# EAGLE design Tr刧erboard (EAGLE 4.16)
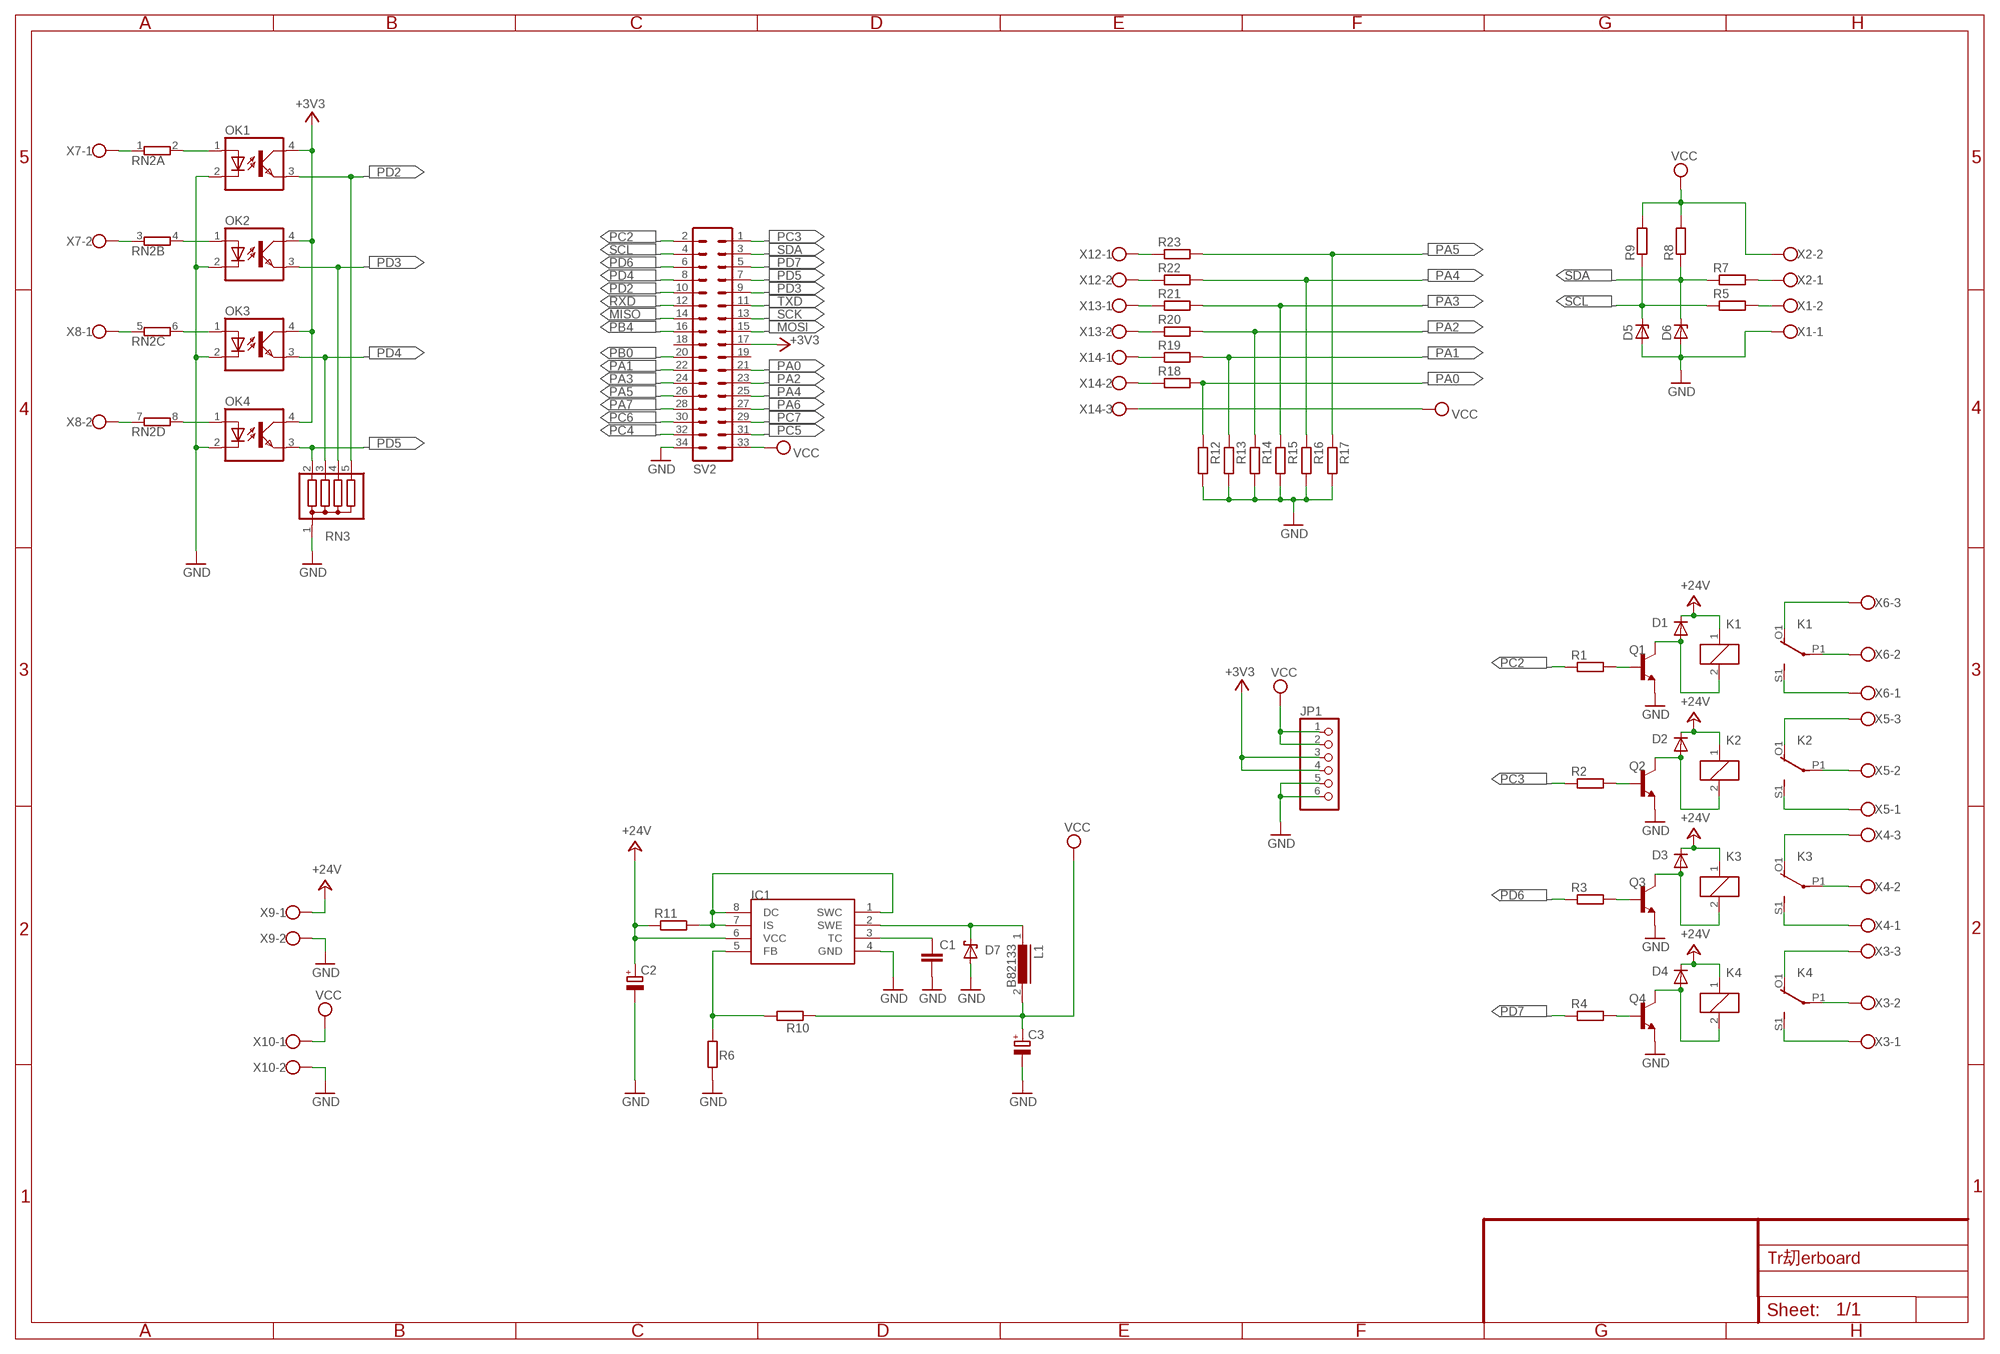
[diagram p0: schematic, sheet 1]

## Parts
C1  C-EU025-024X044  [C025-024X044]
C2  CPOL-EUE5-8.5  [E5-8,5]
C3  CPOL-EUE5-8.5  [E5-8,5]
D1  1N4148  [DO35-10]
D2  1N4148  [DO35-10]
D3  1N4148  [DO35-10]
D4  1N4148  [DO35-10]
D5  1N821  [DO35Z10]
D6  1N821  [DO35Z10]
D7  BAT49  [DO41-10]
IC1  MC34063AP  [DIL08]
JP1  PINHD-1X6  [1X06]
K1  4052  [F4052]
K2  4052  [F4052]
K3  4052  [F4052]
K4  4052  [F4052]
L1  B82133  [SUKW3-27]
OK1  PC817  [DIL04]
OK2  PC817  [DIL04]
OK3  PC817  [DIL04]
OK4  PC817  [DIL04]
Q1  BC337  [TO92]
Q2  BC337  [TO92]
Q3  BC337  [TO92]
Q4  BC337  [TO92]
R1  R-EU_0207/10  [0207/10]
R2  R-EU_0207/10  [0207/10]
R3  R-EU_0207/10  [0207/10]
R4  R-EU_0207/10  [0207/10]
R5  R-EU_0207/10  [0207/10]
R6  R-EU_0207/10  [0207/10]
R7  R-EU_0207/10  [0207/10]
R8  R-EU_0207/10  [0207/10]
R9  R-EU_0207/10  [0207/10]
R10  R-EU_0207/10  [0207/10]
R11  R-EU_0613/15  [P0613/15]
R12  R-EU_0207/10  [0207/10]
R13  R-EU_0207/10  [0207/10]
R14  R-EU_0207/10  [0207/10]
R15  R-EU_0207/10  [0207/10]
R16  R-EU_0207/10  [0207/10]
R17  R-EU_0207/10  [0207/10]
R18  R-EU_0207/10  [0207/10]
R19  R-EU_0207/10  [0207/10]
R20  R-EU_0207/10  [0207/10]
R21  R-EU_0207/10  [0207/10]
R22  R-EU_0207/10  [0207/10]
R23  R-EU_0207/10  [0207/10]
RN2  E4R  [SIL8]
RN3  G04R  [SIL5]
SV2  MA17-2  [MA17-2]
X1  W237-02P  [W237-132]
X2  W237-02P  [W237-132]
X3  W237-103  [W237-103]
X4  W237-103  [W237-103]
X5  W237-103  [W237-103]
X6  W237-103  [W237-103]
X7  W237-02P  [W237-132]
X8  W237-02P  [W237-132]
X9  W237-02P  [W237-132]
X10  W237-02P  [W237-132]
X12  W237-02P  [W237-132]
X13  W237-02P  [W237-132]
X14  W237-3E  [W237-3E]

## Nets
+3V3: JP1.3 JP1.4 OK1.4(COL) OK2.4(COL) OK3.4(COL) OK4.4(COL) SV2.17
+24V: C2.+ D1.C D2.C D3.C D4.C IC1.6(VCC) K1.1 K2.1 K3.1 K4.1 R11.1 X9.1
GND: C1.2 C2.- C3.- D5.A D6.A D7.A IC1.4(GND) JP1.5 JP1.6 OK1.2(C) OK2.2(C) OK3.2(C) OK4.2(C) Q1.1(E) Q2.1(E) Q3.1(E) Q4.1(E) R6.1 R12.2 R13.2 R14.2 R15.2 R16.2 R17.2 RN3.1 SV2.34 X1.1 X9.2 X10.2
MISO: SV2.14
MOSI: SV2.15
N$1: R5.2 X1.2
N$2: K2.P1(2:P) X5.2
N$3: K1.P1(2:P) X6.2
N$4: RN2.3 X7.2
N$5: RN2.5 X8.1
N$6: RN2.7 X8.2
N$7: IC1.5(FB) R6.2 R10.2
N$8: C1.1 IC1.3(TC)
N$9: D7.C IC1.2(SWE) L1.1
N$10: IC1.1(SWC) IC1.7(IS) IC1.8(DC) R11.2
N$11: R7.2 X2.1
N$12: Q4.2(B) R4.2
N$13: K4.S1(2:S) X3.1
N$14: K4.O1(2:O) X3.3
N$15: K3.S1(2:S) X4.1
N$16: K3.O1(2:O) X4.3
N$17: K2.S1(2:S) X5.1
N$18: K2.O1(2:O) X5.3
N$19: K1.S1(2:S) X6.1
N$20: K1.O1(2:O) X6.3
N$21: Q3.2(B) R3.2
N$22: Q2.2(B) R2.2
N$23: Q1.2(B) R1.2
N$24: R23.1 X12.1
N$25: R22.1 X12.2
N$26: R21.1 X13.1
N$27: R20.1 X13.2
N$28: K4.P1(2:P) X3.2
N$29: K3.P1(2:P) X4.2
N$30: R19.1 X14.1
N$31: OK1.1(A) RN2.2
N$32: OK2.1(A) RN2.4
N$33: R18.1 X14.2
N$39: OK3.1(A) RN2.6
N$40: OK4.1(A) RN2.8
N$41: RN2.1 X7.1
PA0: R12.1 R18.2 SV2.21
PA1: R13.1 R19.2 SV2.22
PA2: R14.1 R20.2 SV2.23
PA3: R15.1 R21.2 SV2.24
PA4: R16.1 R22.2 SV2.25
PA5: R17.1 R23.2 SV2.26
PA6: SV2.27
PA7: SV2.28
PB0: SV2.20
PB4: SV2.16
PC2: R1.1 SV2.2
PC3: R2.1 SV2.1
PC4: SV2.32
PC5: SV2.31
PC6: SV2.30
PC7: SV2.29
PD2: OK1.3(EMIT) RN3.5 SV2.10
PD3: OK2.3(EMIT) RN3.4 SV2.9
PD4: OK3.3(EMIT) RN3.3 SV2.8
PD5: OK4.3(EMIT) RN3.2 SV2.7
PD6: R3.1 SV2.6
PD7: R4.1 SV2.5
REL3: D4.A K4.2 Q4.3(C)
REL4: D3.A K3.2 Q3.3(C)
REL5: D2.A K2.2 Q2.3(C)
REL6: D1.A K1.2 Q1.3(C)
RXD: SV2.12
SCK: SV2.13
SCL: D5.C R5.1 R9.1 SV2.4
SDA: D6.C R7.1 R8.1 SV2.3
TXD: SV2.11
VCC: C3.+ JP1.1 JP1.2 L1.2 R8.2 R9.2 R10.1 SV2.33 X2.2 X10.1 X14.3
Unconnected: K1.O2(3:O) K1.P2(3:P) K1.S2(3:S) K2.O2(3:O) K2.P2(3:P) K2.S2(3:S) K3.O2(3:O) K3.P2(3:P) K3.S2(3:S) K4.O2(3:O) K4.P2(3:P) K4.S2(3:S) SV2.18 SV2.19

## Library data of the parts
C1 = rcl:C-EU: CAPACITOR, European symbol
C2 C3 = rcl:CPOL-EU: POLARIZED CAPACITOR, European symbol
D1-D4 = diode:1N4148: DIODE
D5 D6 = diode:1N821: Reference DIODE
D7 = diode:BAT49: DIODE
IC1 = mc34063:MC34063
JP1 = pinhead:PINHD-1X6: PIN HEADER
K1-K4 = relay:4052: RELAY 2 x switch, Finder
L1 = inductors:B82133: INDUCTOR
OK1-OK4 = optocoupler:PC817: SHARP OPTO COUPLER
Q1-Q4 = transistor-npn:BC337*: NPN Transistor
R1-R23 = rcl:R-EU_: RESISTOR, European symbol
RN2 = resistor-sil:E4R: SIL RESISTOR
RN3 = resistor-sil:G04R: SIL RESISTOR
SV2 = con-lstb:MA17-2: PIN HEADER
X1 X2 X7-X10 X12 X13 = con-wago-508:W237-02P: WAGO SREW CLAMP
X3-X6 = con-wago-500:W237-103: WAGO SCREW CLAMP
X14 = con-wago-508:W237-3E: WAGO SREW CLAMP

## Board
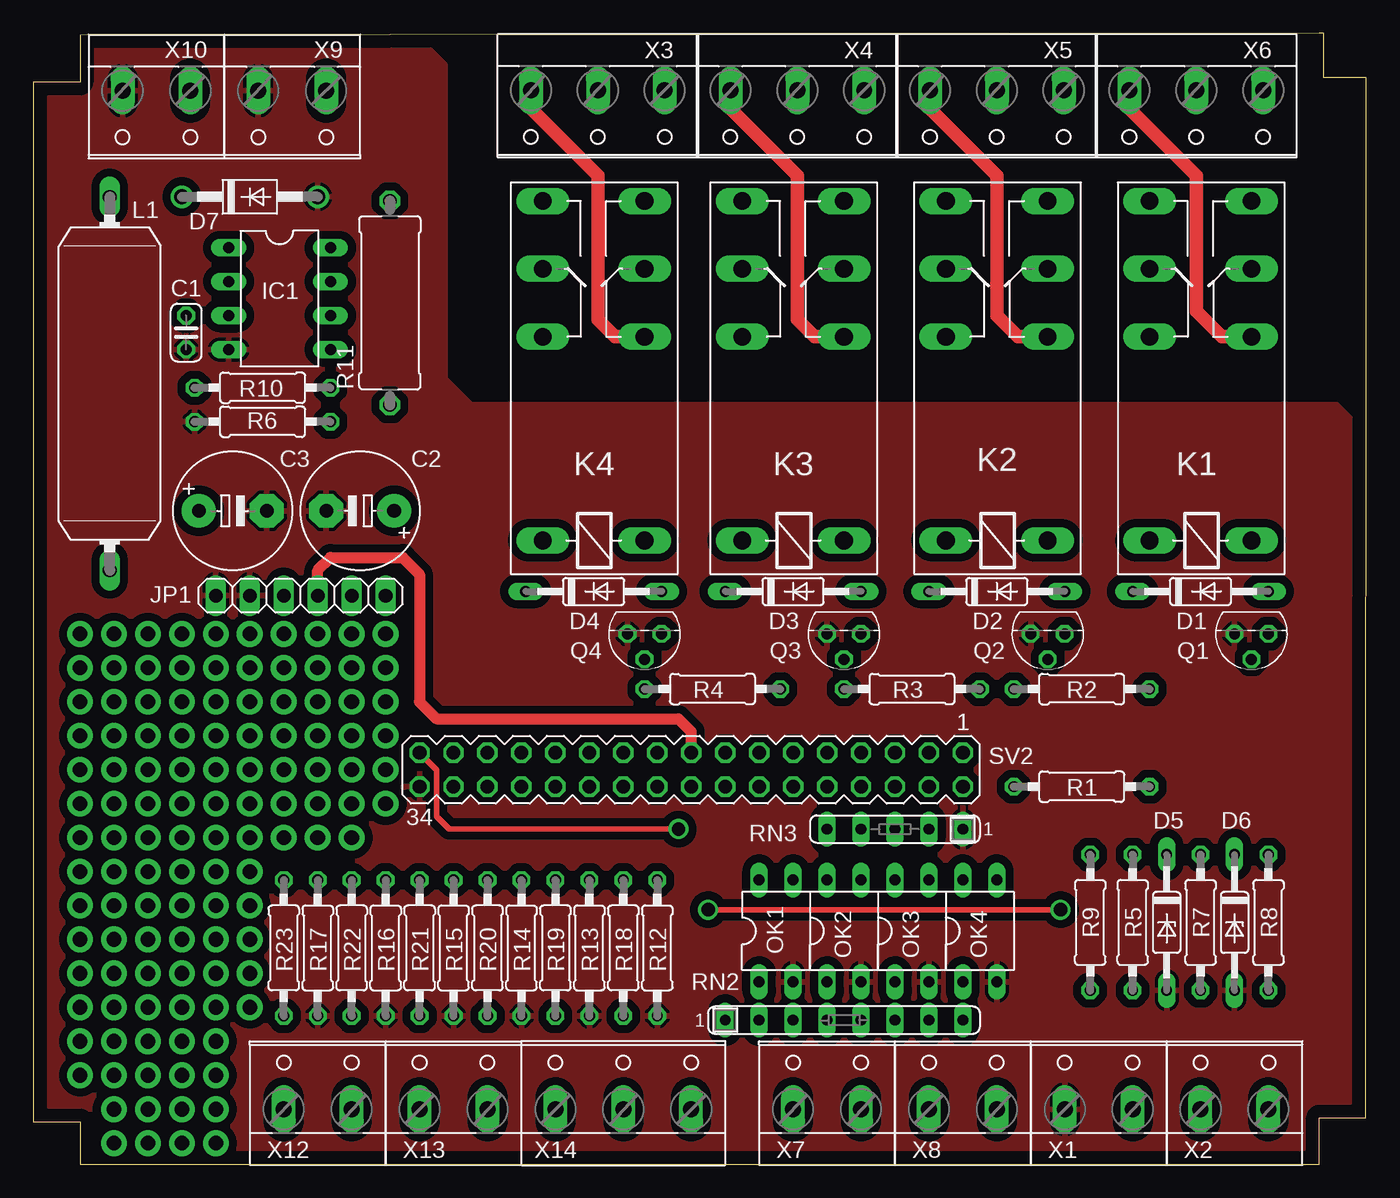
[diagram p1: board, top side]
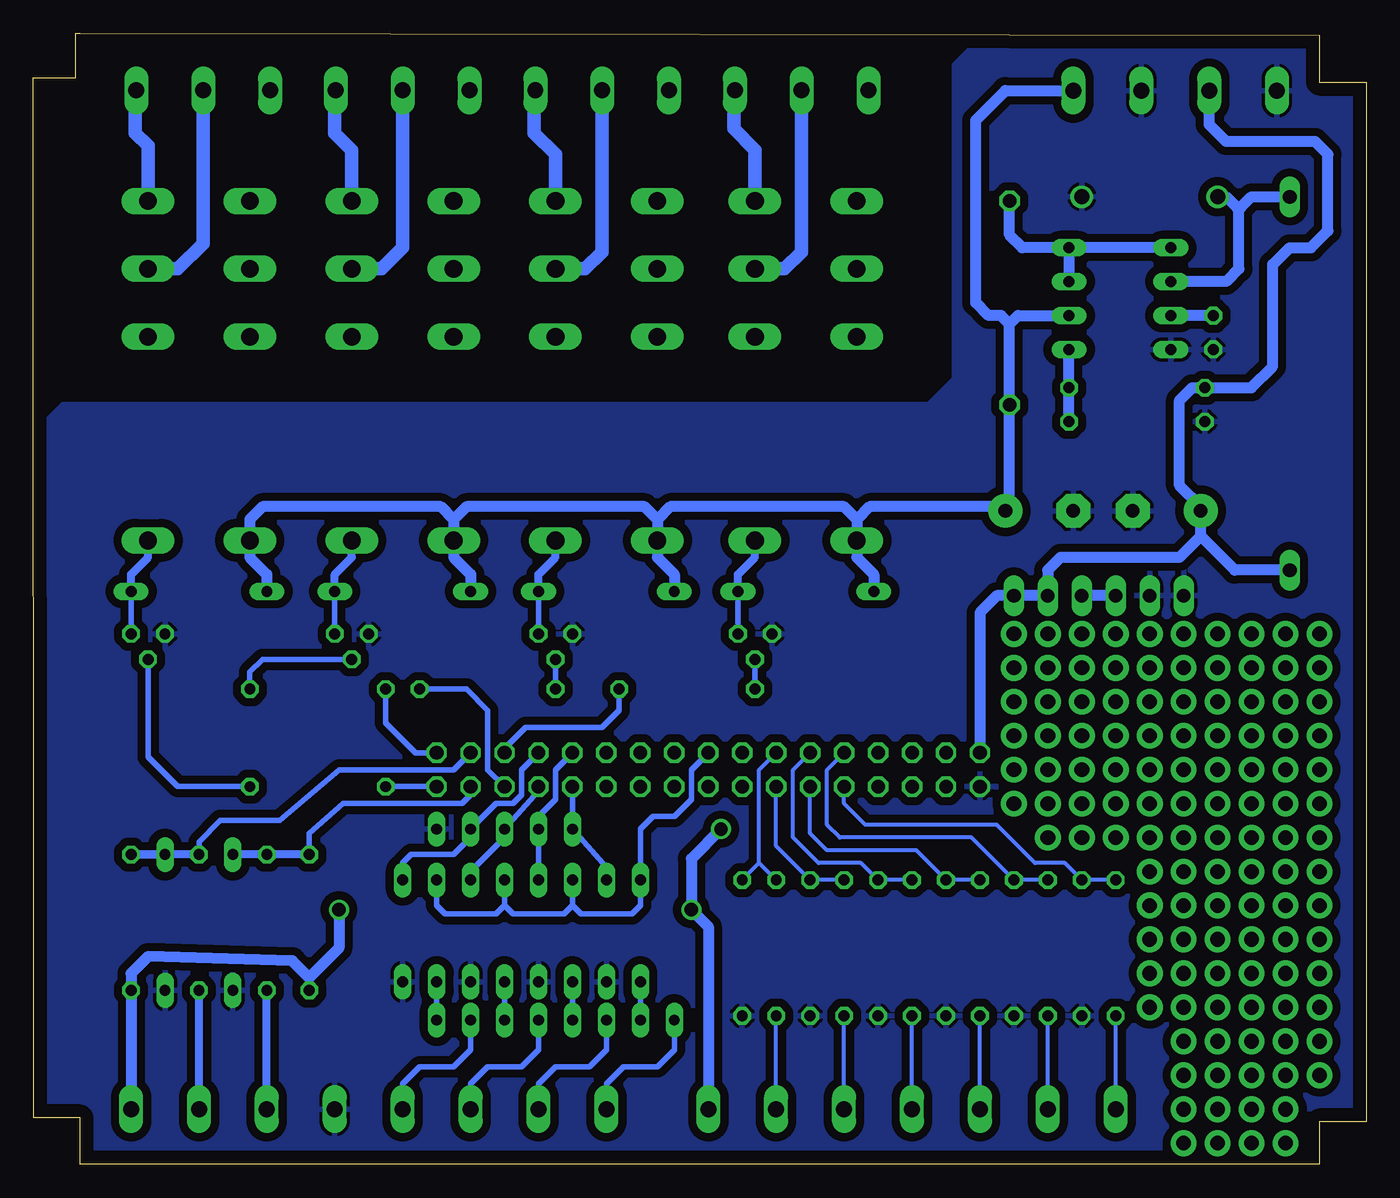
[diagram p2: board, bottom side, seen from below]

Size 99.69 x 84.61 mm. Coordinates in mm from the lower left corner, seen from the top.
Outline: 0,3.17 3.49,3.17 3.49,0 96.2,0 96.2,3.48 99.68,3.48 99.68,3.66 99.69,81.28 96.52,81.28 96.52,84.61 96.18,84.61 3.49,84.45 3.49,80.97 0,80.97 0,3.17
Copper layers (1*16): Top 0.035mm / dielectric 1.5mm / Bottom 0.035mm
Design rules "default": minimum track width 10mil, minimum drill 24mil, track to track 8mil, track to pad 8mil, pad to pad 8mil, via to via 8mil, smd to smd 8mil, copper to edge 40mil, drill to drill 8mil, minimum pad ring 10mil, minimum via ring 8mil, stop-mask expansion 4mil, vias tented up to drill 0mil, thermal gap 10mil

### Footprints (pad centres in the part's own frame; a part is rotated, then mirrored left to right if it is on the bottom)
C025-024X044 = drill 0.813 octagon: 1 -1.27,0; 2 1.27,0
E5-8,5 = drill 1.016 pad 2.54 round: + -2.54,0 | drill 1.016 pad 2.54 octagon: - 2.54,0
DO35-10 = drill 0.813 long: A 5.08,0; C -5.08,0
DO35Z10 = drill 0.813 long: A 5.08,0; C -5.08,0
DO41-10 = drill 1.118 round: A 5.08,0; C -5.08,0
DIL08 = drill 0.813 long: 1 -3.81,-3.81; 2 -1.27,-3.81; 3 1.27,-3.81; 4 3.81,-3.81; 5 3.81,3.81; 6 1.27,3.81; 7 -1.27,3.81; 8 -3.81,3.81
1X06 = drill 1.016 long: 1 -6.35,0; 2 -3.81,0; 3 -1.27,0; 4 1.27,0; 5 3.81,0; 6 6.35,0
F4052 = drill 1.321 long: 1 -3.81,3.81; 2 -3.81,-3.81; O1 11.43,-3.81; O2 11.43,3.81; P1 16.51,-3.81; P2 16.51,3.81; S1 21.59,-3.81; S2 21.59,3.81
SUKW3-27 = drill 1.016 long: 1 -13.97,0; 2 13.97,0
DIL04 = drill 0.813 long: 1 -1.27,-3.81; 2 1.27,-3.81; 3 1.27,3.81; 4 -1.27,3.81
TO92 = drill 0.813 octagon: 1 1.27,0; 2 0,1.905; 3 -1.27,0
0207/10 = drill 0.813 octagon: 1 -5.08,0; 2 5.08,0
P0613/15 = drill 1.016 octagon: 1 -7.62,0; 2 7.62,0
SIL8 = drill 0.813 long: 1 -8.89,0; 2 -6.35,0; 3 -3.81,0; 4 -1.27,0; 5 1.27,0; 6 3.81,0; 7 6.35,0; 8 8.89,0
SIL5 = drill 0.813 long: 1 -5.08,0; 2 -2.54,0; 3 0,0; 4 2.54,0; 5 5.08,0
MA17-2 = drill 1.016 octagon: 1 -20.32,-1.27; 2 -20.32,1.27; 3 -17.78,-1.27; 4 -17.78,1.27; 5 -15.24,-1.27; 6 -15.24,1.27; 7 -12.7,-1.27; 8 -12.7,1.27; 9 -10.16,-1.27; 10 -10.16,1.27; 11 -7.62,-1.27; 12 -7.62,1.27; 13 -5.08,-1.27; 14 -5.08,1.27; 15 -2.54,-1.27; 16 -2.54,1.27; 17 0,-1.27; 18 0,1.27; 19 2.54,-1.27; 20 2.54,1.27; 21 5.08,-1.27; 22 5.08,1.27; 23 7.62,-1.27; 24 7.62,1.27; 25 10.16,-1.27; 26 10.16,1.27; 27 12.7,-1.27; 28 12.7,1.27; 29 15.24,-1.27; 30 15.24,1.27; 31 17.78,-1.27; 32 17.78,1.27; 33 20.32,-1.27; 34 20.32,1.27
W237-132 = drill 1.194 long: 1 -2.54,-0.635; 2 2.54,-0.635
W237-103 = drill 1.194 long: 1 -5,-1.29; 2 0,-1.29; 3 5,-1.29
W237-3E = drill 1.194 long: 1 -5.08,-0.635; 2 0,-0.635; 3 5.08,-0.635

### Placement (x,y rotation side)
C1  11.42,62.23 270 top
C2  24.44,48.89 180 top
C3  14.92,48.89 0 top
D1  87.31,42.86 0 top
D2  72.07,42.86 0 top
D3  56.83,42.86 0 top
D4  41.9,42.86 0 top
D5  84.77,18.1 270 top
D6  89.85,18.1 270 top
D7  16.19,72.39 0 top
IC1  18.41,64.77 270 top
JP1  20,42.54 180 top
K1  87.31,50.48 90 top
K2  72.07,50.48 90 top
K3  56.83,50.48 90 top
K4  41.9,50.48 90 top
L1  5.71,58.42 270 top
OK1  55.56,17.46 0 top
OK2  60.64,17.46 0 top
OK3  65.72,17.46 0 top
OK4  70.8,17.46 0 top
Q1  91.12,39.69 180 top
Q2  75.88,39.69 180 top
Q3  60.64,39.69 180 top
Q4  45.71,39.69 180 top
R1  78.42,28.26 0 top
R2  78.42,35.56 0 top
R3  65.72,35.56 180 top
R4  50.79,35.56 180 top
R5  82.23,18.1 270 top
R6  17.14,55.56 0 top
R7  87.31,18.1 270 top
R8  92.39,18.1 270 top
R9  79.05,18.1 270 top
R10  17.14,58.1 0 top
R11  26.67,64.45 90 top
R12  46.67,16.19 270 top
R13  41.59,16.19 270 top
R14  36.51,16.19 270 top
R15  31.43,16.19 270 top
R16  26.35,16.19 270 top
R17  21.27,16.19 270 top
R18  44.13,16.19 90 top
R19  39.05,16.19 90 top
R20  33.97,16.19 90 top
R21  28.89,16.19 90 top
R22  23.81,16.19 90 top
R23  18.73,16.19 90 top
RN2  60.64,10.79 0 top
RN3  64.45,25.08 180 top
SV2  49.21,29.53 180 top
X1  79.69,4.76 0 top
X2  89.85,4.76 0 top
X3  42.22,79.06 180 top
X4  57.14,79.06 180 top
X5  72.07,79.06 180 top
X6  86.99,79.06 180 top
X7  59.37,4.76 0 top
X8  69.53,4.76 0 top
X9  19.36,79.69 180 top
X10  9.2,79.69 180 top
X12  21.27,4.76 0 top
X13  31.43,4.76 0 top
X14  44.13,4.76 0 top

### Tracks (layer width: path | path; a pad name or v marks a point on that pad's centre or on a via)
+3V3
  Top 0.813: JP1.3 21.27,44.45 22.22,45.4 27.62,45.4 28.89,44.13 28.89,34.61 30.16,33.34 48.25,33.34 49.21,32.39 SV2.17
  Bottom 0.406: 59.37,19.37 58.73,18.73 54.92,18.73 54.29,19.37 OK1.4 54.29,25.08 53.34,26.03 51.75,26.03 50.48,27.3 50.48,29.53 SV2.17 | 59.37,19.37 OK2.4 | 59.37,19.37 60,18.73 63.81,18.73 64.45,19.37 | 64.45,19.37 OK3.4 | 64.45,19.37 65.08,18.73 68.89,18.73 69.53,19.37 OK4.4
  Bottom 0.813: JP1.4 JP1.3
+24V
  Bottom 0.406: 38.09,45.4 K4.1 | 53.02,45.4 K3.1 53.02,48.26 | 68.26,45.4 K2.1 68.26,48.26 | 83.5,46.35 K1.1
  Bottom 0.813: D4.C 36.82,44.13 38.09,45.4 38.09,48.26 | D3.C 51.75,44.13 53.02,45.4 53.02,48.26 | D2.C 66.99,44.13 68.26,45.4 68.26,48.26 | D1.C 82.23,44.13 83.5,45.4 83.5,46.35 83.5,48.26 82.55,49.21 69.21,49.21 68.26,48.26 | 38.09,48.26 39.05,49.21 52.06,49.21 53.02,48.26 | 53.02,48.26 53.97,49.21 67.31,49.21 68.26,48.26 | 38.09,48.26 37.14,49.21 26.98,49.21 C2.+ 26.67,49.21 R11.1 26.67,62.86 | X9.1 26.98,80.33 29.21,78.1 29.21,64.45 28.25,63.5 27.3,63.5 26.67,62.86 | IC1.6 26.03,63.5 26.67,62.86
GND
  pour Bottom (isolate 0.61): -0.01,84.45 28.57,84.45 30.79,82.23 30.79,58.74 32.7,56.83 97.47,56.83 99.69,54.61 99.69,0 -0.01,0
  pour Top (isolate 0.61): -0.01,84.45 28.57,84.45 30.79,82.23 30.79,58.74 32.7,56.83 97.47,56.83 99.69,54.61 99.69,0 -0.01,0
N$1
  Bottom 0.61: X1.2 R5.2
N$2
  Bottom 1.016: X5.2 72.07,68.58 73.66,66.99 K2.P1
N$3
  Bottom 1.016: X6.2 86.99,68.9 88.9,66.99 K1.P1
N$4
  Bottom 0.406: RN2.3 56.83,8.57 58.1,7.3 60.64,7.3 61.91,6.03 X7.2
N$5
  Bottom 0.406: RN2.5 61.91,8.57 63.18,7.3 65.72,7.3 66.99,6.03 X8.1
N$6
  Bottom 0.406: RN2.7 66.99,8.57 68.26,7.3 70.8,7.3 72.07,6.03 X8.2
N$7
  Bottom 0.813: IC1.5 R10.2 R6.2
N$8
  Bottom 0.813: C1.1 IC1.3
N$9
  Bottom 0.813: IC1.2 10.47,66.04 9.52,66.99 9.52,71.44 9.68,71.6 | 9.68,71.6 10.47,72.39 D7.C | 9.68,71.6 9.36,71.6 8.57,72.39 L1.1
N$10
  Bottom 0.813: IC1.8 25.71,68.58 26.67,69.53 R11.2 | IC1.8 IC1.7 | IC1.1 IC1.8
N$11
  Bottom 0.61: X2.1 R7.2
N$12
  Bottom 0.406: R4.2 Q4.2
N$13
  Bottom 0.406: 47.3,80.33 47.28,80.35 X3.1
  Bottom 1.016: K4.S1 45.71,75.88 47.3,77.47 47.3,80.33
N$14
  Top 1.016: X3.3 37.22,78.98 42.22,73.98 42.22,63.18 43.49,61.91 K4.O1
N$15
  Bottom 0.406: 62.22,80.33 62.24,80.35 X4.1
  Bottom 1.016: K3.S1 60.64,75.56 62.22,77.15 62.22,80.33
N$16
  Top 1.016: X4.3 52.14,78.98 57.14,73.98 57.14,63.18 58.41,61.91 K3.O1
N$17
  Bottom 0.406: 77.15,80.33 77.13,80.35 X5.1
  Bottom 1.016: K2.S1 75.88,75.88 77.15,77.15 77.15,80.33
N$18
  Top 1.016: X5.3 67.07,78.98 72.07,73.98 72.07,63.5 73.66,61.91 K2.O1
N$19
  Bottom 0.406: 92.07,80.33 92.05,80.35 X6.1
  Bottom 1.016: K1.S1 91.12,76.2 92.07,77.15 92.07,80.33
N$20
  Top 1.016: X6.3 81.99,78.98 86.99,73.98 86.99,63.82 88.9,61.91 K1.O1
N$21
  Bottom 0.406: R3.2 Q3.2
N$22
  Bottom 0.406: Q2.2 82.55,37.78 83.5,36.83 R2.2
N$23
  Bottom 0.406: R1.2 88.9,28.26 91.12,30.48 Q1.2
N$24
  Bottom 0.305: X12.1 R23.1
N$25
  Bottom 0.305: X12.2 R22.1
N$26
  Bottom 0.305: X13.1 R21.1
N$27
  Bottom 0.305: X13.2 R20.1
N$28
  Bottom 1.016: X3.2 42.22,68.26 43.49,66.99 K4.P1
N$29
  Bottom 1.016: X4.2 57.14,68.26 58.41,66.99 K3.P1
N$30
  Bottom 0.305: X14.1 R19.1
N$31
  Bottom 0.406: RN2.2 OK1.1
N$32
  Bottom 0.406: RN2.4 OK2.1
N$33
  Bottom 0.305: X14.2 R18.1
N$34  (via drill 1.1 pad 1.93)
  other vias: 8.57,6.67
N$35  (via drill 1.1 pad 1.93)
  other vias: 11.11,6.67
N$36  (via drill 1.1 pad 1.93)
  other vias: 23.81,39.69
N$37  (via drill 1.1 pad 1.93)
  other vias: 23.81,37.15
N$38  (via drill 1.1 pad 1.93)
  other vias: 21.27,39.69
N$39
  Bottom 0.406: RN2.6 OK3.1
N$40
  Bottom 0.406: RN2.8 OK4.1
N$41
  Bottom 0.406: RN2.1 51.75,8.57 53.02,7.3 55.56,7.3 56.83,6.03 X7.1
N$42  (via drill 1.1 pad 1.93)
  other vias: 21.27,37.15
N$43  (via drill 1.1 pad 1.93)
  other vias: 18.73,39.69
N$44  (via drill 1.1 pad 1.93)
  other vias: 18.73,37.15
N$45  (via drill 1.1 pad 1.93)
  other vias: 16.19,39.69
N$46  (via drill 1.1 pad 1.93)
  other vias: 16.19,37.15
N$47  (via drill 1.1 pad 1.93)
  other vias: 13.65,39.69
N$48  (via drill 1.1 pad 1.93)
  other vias: 13.65,37.15
N$49  (via drill 1.1 pad 1.93)
  other vias: 11.11,39.69
N$50  (via drill 1.1 pad 1.93)
  other vias: 11.11,37.15
N$51  (via drill 1.1 pad 1.93)
  other vias: 8.57,37.15
N$52  (via drill 1.1 pad 1.93)
  other vias: 8.57,39.69
N$53  (via drill 1.1 pad 1.93)
  other vias: 6.03,39.69
N$54  (via drill 1.1 pad 1.93)
  other vias: 6.03,37.15
N$55  (via drill 1.1 pad 1.93)
  other vias: 3.49,37.15
N$56  (via drill 1.1 pad 1.93)
  other vias: 3.49,39.69
N$57  (via drill 1.1 pad 1.93)
  other vias: 3.49,34.61
N$58  (via drill 1.1 pad 1.93)
  other vias: 6.03,34.61
N$59  (via drill 1.1 pad 1.93)
  other vias: 8.57,34.61
N$60  (via drill 1.1 pad 1.93)
  other vias: 11.11,34.61
N$61  (via drill 1.1 pad 1.93)
  other vias: 13.65,34.61
N$62  (via drill 1.1 pad 1.93)
  other vias: 16.19,34.61
N$63  (via drill 1.1 pad 1.93)
  other vias: 18.73,34.61
N$64  (via drill 1.1 pad 1.93)
  other vias: 21.27,34.61
N$65  (via drill 1.1 pad 1.93)
  other vias: 23.81,34.61
N$66  (via drill 1.1 pad 1.93)
  other vias: 13.65,6.67
N$67  (via drill 1.1 pad 1.93)
  other vias: 16.19,11.75
N$68  (via drill 1.1 pad 1.93)
  other vias: 16.19,14.29
N$69  (via drill 1.1 pad 1.93)
  other vias: 16.19,16.83
N$70  (via drill 1.1 pad 1.93)
  other vias: 23.81,32.07
N$71  (via drill 1.1 pad 1.93)
  other vias: 23.81,29.53
N$72  (via drill 1.1 pad 1.93)
  other vias: 23.81,26.99
N$73  (via drill 1.1 pad 1.93)
  other vias: 21.27,26.99
N$74  (via drill 1.1 pad 1.93)
  other vias: 21.27,29.53
N$75  (via drill 1.1 pad 1.93)
  other vias: 21.27,32.07
N$76  (via drill 1.1 pad 1.93)
  other vias: 18.73,32.07
N$77  (via drill 1.1 pad 1.93)
  other vias: 18.73,29.53
N$78  (via drill 1.1 pad 1.93)
  other vias: 18.73,26.99
N$79  (via drill 1.1 pad 1.93)
  other vias: 16.19,26.99
N$80  (via drill 1.1 pad 1.93)
  other vias: 16.19,29.53
N$81  (via drill 1.1 pad 1.93)
  other vias: 16.19,32.07
N$82  (via drill 1.1 pad 1.93)
  other vias: 13.65,32.07
N$83  (via drill 1.1 pad 1.93)
  other vias: 13.65,29.53
N$84  (via drill 1.1 pad 1.93)
  other vias: 13.65,26.99
N$85  (via drill 1.1 pad 1.93)
  other vias: 11.11,26.99
N$86  (via drill 1.1 pad 1.93)
  other vias: 11.11,29.53
N$87  (via drill 1.1 pad 1.93)
  other vias: 11.11,32.07
N$88  (via drill 1.1 pad 1.93)
  other vias: 8.57,32.07
N$89  (via drill 1.1 pad 1.93)
  other vias: 8.57,29.53
N$90  (via drill 1.1 pad 1.93)
  other vias: 8.57,26.99
N$91  (via drill 1.1 pad 1.93)
  other vias: 6.03,26.99
N$92  (via drill 1.1 pad 1.93)
  other vias: 6.03,29.53
N$93  (via drill 1.1 pad 1.93)
  other vias: 6.03,32.07
N$94  (via drill 1.1 pad 1.93)
  other vias: 3.49,32.07
N$95  (via drill 1.1 pad 1.93)
  other vias: 3.49,29.53
N$96  (via drill 1.1 pad 1.93)
  other vias: 3.49,26.99
N$97  (via drill 1.1 pad 1.93)
  other vias: 23.81,24.45
N$98  (via drill 1.1 pad 1.93)
  other vias: 21.27,24.45
N$99  (via drill 1.1 pad 1.93)
  other vias: 18.73,24.45
N$100  (via drill 1.1 pad 1.93)
  other vias: 16.19,24.45
N$101  (via drill 1.1 pad 1.93)
  other vias: 13.65,24.45
N$102  (via drill 1.1 pad 1.93)
  other vias: 11.11,24.45
N$103  (via drill 1.1 pad 1.93)
  other vias: 8.57,24.45
N$104  (via drill 1.1 pad 1.93)
  other vias: 6.03,24.45
N$105  (via drill 1.1 pad 1.93)
  other vias: 3.49,24.45
N$106  (via drill 1.1 pad 1.93)
  other vias: 16.19,19.37
N$107  (via drill 1.1 pad 1.93)
  other vias: 6.03,4.13
N$109  (via drill 1.1 pad 1.93)
  other vias: 3.49,6.67
N$110  (via drill 1.1 pad 1.93)
  other vias: 6.03,6.67
N$111  (via drill 1.1 pad 1.93)
  other vias: 13.65,9.21
N$112  (via drill 1.1 pad 1.93)
  other vias: 13.65,11.75
N$113  (via drill 1.1 pad 1.93)
  other vias: 13.65,14.29
N$114  (via drill 1.1 pad 1.93)
  other vias: 13.65,16.83
N$115  (via drill 1.1 pad 1.93)
  other vias: 13.65,19.37
N$116  (via drill 1.1 pad 1.93)
  other vias: 11.11,9.21
N$117  (via drill 1.1 pad 1.93)
  other vias: 11.11,11.75
N$118  (via drill 1.1 pad 1.93)
  other vias: 11.11,14.29
N$119  (via drill 1.1 pad 1.93)
  other vias: 11.11,16.83
N$120  (via drill 1.1 pad 1.93)
  other vias: 11.11,19.37
N$121  (via drill 1.1 pad 1.93)
  other vias: 8.57,19.37
N$122  (via drill 1.1 pad 1.93)
  other vias: 8.57,16.83
N$123  (via drill 1.1 pad 1.93)
  other vias: 8.57,14.29
N$124  (via drill 1.1 pad 1.93)
  other vias: 8.57,11.75
N$125  (via drill 1.1 pad 1.93)
  other vias: 8.57,9.21
N$126  (via drill 1.1 pad 1.93)
  other vias: 8.57,4.13
N$127  (via drill 1.1 pad 1.93)
  other vias: 13.65,4.13
N$128  (via drill 1.1 pad 1.93)
  other vias: 11.11,4.13
N$129  (via drill 1.1 pad 1.93)
  other vias: 6.03,9.21
N$130  (via drill 1.1 pad 1.93)
  other vias: 3.49,9.21
N$131  (via drill 1.1 pad 1.93)
  other vias: 3.49,11.75
N$132  (via drill 1.1 pad 1.93)
  other vias: 6.03,11.75
N$133  (via drill 1.1 pad 1.93)
  other vias: 3.49,14.29
N$134  (via drill 1.1 pad 1.93)
  other vias: 6.03,14.29
N$135  (via drill 1.1 pad 1.93)
  other vias: 6.03,16.83
N$136  (via drill 1.1 pad 1.93)
  other vias: 3.49,16.83
N$137  (via drill 1.1 pad 1.93)
  other vias: 3.49,19.37
N$138  (via drill 1.1 pad 1.93)
  other vias: 6.03,19.37
N$139  (via drill 1.1 pad 1.93)
  other vias: 3.49,21.91
N$140  (via drill 1.1 pad 1.93)
  other vias: 6.03,21.91
N$141  (via drill 1.1 pad 1.93)
  other vias: 8.57,21.91
N$142  (via drill 1.1 pad 1.93)
  other vias: 11.11,21.91
N$143  (via drill 1.1 pad 1.93)
  other vias: 13.65,21.91
N$144  (via drill 1.1 pad 1.93)
  other vias: 16.19,21.91
N$145  (via drill 1.1 pad 1.93)
  other vias: 13.65,1.59
N$146  (via drill 1.1 pad 1.93)
  other vias: 26.35,26.99
N$147  (via drill 1.1 pad 1.93)
  other vias: 26.35,29.53
N$148  (via drill 1.1 pad 1.93)
  other vias: 26.35,32.07
N$149  (via drill 1.1 pad 1.93)
  other vias: 26.35,34.61
N$150  (via drill 1.1 pad 1.93)
  other vias: 26.35,37.15
N$151  (via drill 1.1 pad 1.93)
  other vias: 26.35,39.69
N$152  (via drill 1.1 pad 1.93)
  other vias: 11.11,1.59
N$153  (via drill 1.1 pad 1.93)
  other vias: 8.57,1.59
N$154  (via drill 1.1 pad 1.93)
  other vias: 6.03,1.59
PA0
  Bottom 0.305: SV2.21 45.4,29.53 45.4,22.54 | R18.2 45.4,22.54 | 45.4,22.54 R12.1
PA1
  Bottom 0.305: R19.2 R13.1 44.13,23.81 SV2.22
PA2
  Bottom 0.305: R20.2 R14.1 37.78,22.54 40.95,22.54 42.86,24.45 42.86,29.53 SV2.23
PA3
  Bottom 0.305: R21.2 R15.1 33.65,23.49 40.32,23.49 41.59,24.76 SV2.24
PA4
  Bottom 0.305: R22.2 R16.1 29.52,24.45 39.36,24.45 40.32,25.4 40.32,29.53 SV2.25
PA5
  Bottom 0.305: R23.2 20.63,21.27 20.95,20.96 R17.1 22.54,22.54 24.76,22.54 27.62,25.4 37.46,25.4 39.05,26.99 SV2.26
PC2
  Bottom 0.406: SV2.2 R1.1
PC3
  Bottom 0.406: SV2.1 71.12,30.8 73.34,33.02 R2.1
PD2
  Bottom 0.406: SV2.10 RN3.5 56.83,22.23 OK1.3
PD3
  Bottom 0.406: OK2.3 RN3.4 61.91,26.03 60.64,27.3 60.64,29.53 SV2.9
PD4
  Bottom 0.406: SV2.8 61.91,27.94 RN3.3 64.45,24.45 66.99,21.91 OK3.3
PD5
  Bottom 0.406: SV2.7 63.18,29.53 63.18,27.62 63.81,26.99 65.08,26.99 RN3.2 66.99,24.45 68.26,23.18 71.43,23.18 72.07,22.54 OK4.3
PD6
  Bottom 0.406: R3.1 67.31,35.56 65.72,33.97 65.72,29.53 SV2.6
PD7
  Bottom 0.406: SV2.5 64.45,31.12 62.86,32.7 57.14,32.7 55.88,33.97 R4.1
REL3
  Bottom 0.406: Q4.3 D4.A
  Bottom 0.61: D4.A 46.98,44.13 45.71,45.4 K4.2
REL4
  Bottom 0.406: Q3.3 D3.A
  Bottom 0.61: D3.A 61.91,44.13 60.64,45.4 K3.2
REL5
  Bottom 0.406: Q2.3 D2.A
  Bottom 0.61: D2.A 77.15,44.13 75.88,45.4 K2.2
REL6
  Bottom 0.406: Q1.3 D1.A
  Bottom 0.61: D1.A 92.39,44.13 91.12,45.4 K1.2
SCL
  Bottom 0.406: SV2.4 66.99,27.62 67.62,26.99 76.51,26.99 79.05,24.76 R9.1
  Bottom 0.61: R5.1 R9.1 D5.C
SDA
  Bottom 0.406: SV2.3 68.26,29.53 76.83,29.53 81.28,25.72 85.72,25.72 87.31,24.13 R7.1
  Bottom 0.61: R7.1 R8.1 D6.C
VCC  (via drill 1)
  Top 0.406: v50.48,19.05 v76.83,19.05 | v48.25,25.08 31.11,25.08 30.16,26.03 30.16,29.53 SV2.33
  Bottom 0.61: 79.05,13.97 R9.2
  Bottom 0.813: X2.2 R8.2 92.39,14.29 91.12,15.56 80.32,15.24 79.05,13.97 76.83,16.19 v76.83,19.05 | X14.3 49.21,17.78 v50.48,19.05 50.48,22.86 v48.25,25.08 | L1.2 9.84,44.45 12.38,46.99 | 12.38,46.99 C3.+ 12.38,49.21 13.96,50.8 13.96,57.15 13.01,58.1 R10.1 8.57,58.1 6.98,59.69 6.98,67.31 5.71,68.58 4.12,68.58 2.85,69.85 2.85,75.56 3.81,76.52 10.47,76.52 11.74,77.79 X10.1 | 12.38,46.99 13.96,45.4 22.86,45.4 23.81,44.45 JP1.2 JP1.1 27.62,42.54 28.89,41.28 SV2.33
